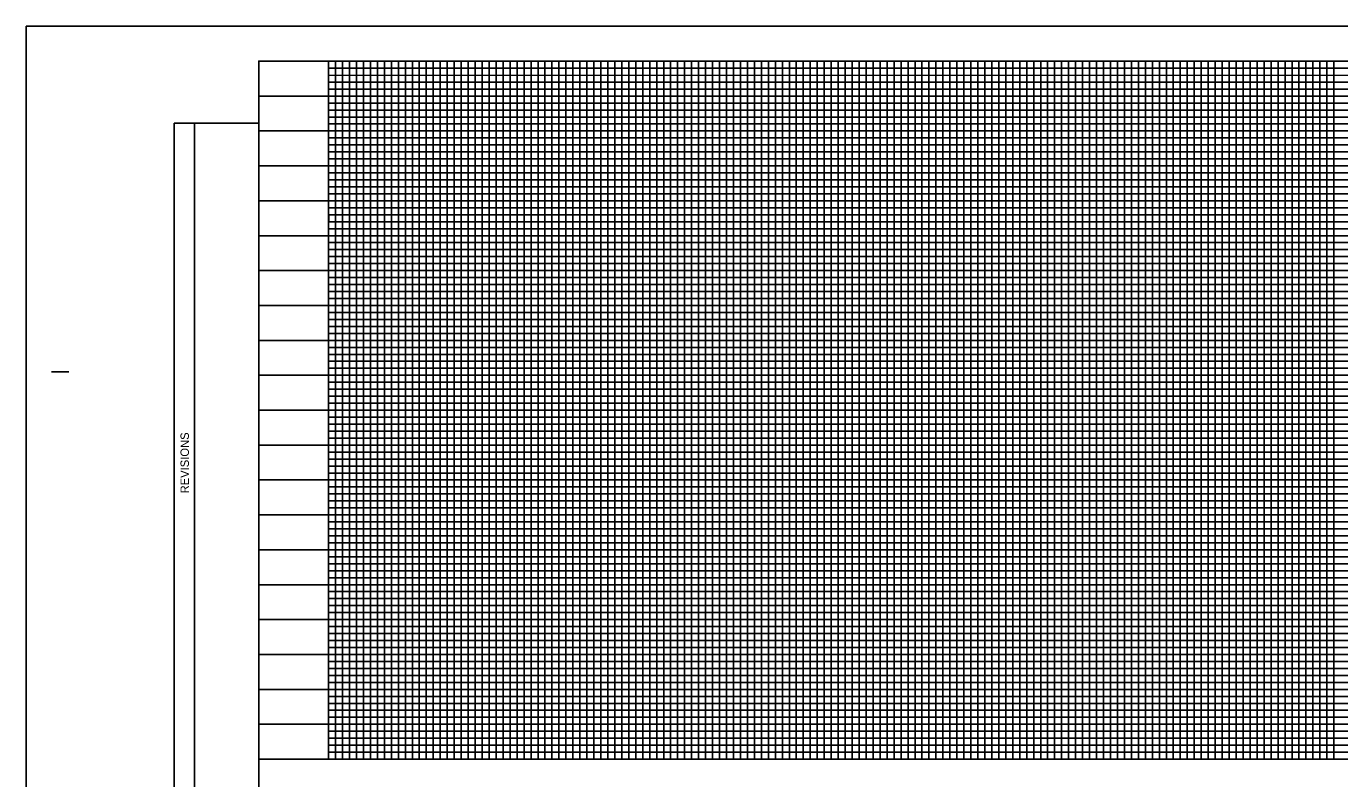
# Model space of a CAD drawing. Extents: x 2431000 to 2534000, y 645879 to 714000.
# Drawn here: x 2466807 to 2467748, y 669403 to 669942 of the extents above; entities that cross this region are included whole.
import ezdxf

# ---------------------------------------------------------------- set-up
doc = ezdxf.new("R2010")
doc.units = 0
for name, color, linetype in [('Sheet Block Revision CELL', 7, 'Continuous'), ('Sheet Clip Boundary CELL', 7, 'Continuous'), ('Sheet Plot Border Outside CELL', 7, 'Continuous'), ('Sheet Profile CELL', 7, 'Continuous'), ('Sheet Profile Grid Major CELL', 7, 'Continuous'), ('Sheet Profile Grid Middle CELL', 7, 'Continuous'), ('Sheet Profile Grid Minor CELL', 7, 'Continuous')]:
    doc.layers.add(name, color=color, linetype=linetype)

msp = doc.modelspace()

# ---------------------------------------------------------------- linework, layer by layer
at = {"layer": 'Sheet Block Revision CELL'}
for p, q in [((2466913.23, 669382.06), (2466913.23, 669872.71)), ((2466973.77, 669872.71), (2466913.23, 669872.71)), ((2466927.77, 669382.06), (2466927.77, 669872.72))]:
    msp.add_line(p, q, dxfattribs=at)
at = {"layer": 'Sheet Clip Boundary CELL'}
msp.add_lwpolyline([(2468456.5, 669779.51), (2468292.45, 669779.51), (2468292.45, 669917.06), (2467023.75, 669917.06), (2467023.75, 669417.06), (2468423.75, 669417.06), (2468423.75, 669779.51)], dxfattribs=at)
at = {"layer": 'Sheet Plot Border Outside CELL'}
msp.add_lwpolyline([(2466807.25, 668842.06), (2468490.75, 668842.06), (2468490.75, 669942.06), (2466807.25, 669942.06)], close=True, dxfattribs=at)
at = {"layer": 'Sheet Profile CELL'}
for p, q in [((2466825.25, 669694.56), (2466837.75, 669694.56)), ((2466973.75, 669417.06), (2468473.75, 669417.06)), ((2466973.75, 669417.06), (2468473.75, 669417.06))]:
    msp.add_line(p, q, dxfattribs=at)
msp.add_lwpolyline([(2468473.75, 669917.06), (2466973.75, 669917.06), (2466973.75, 668867.06), (2468473.75, 668867.06)], close=True, dxfattribs=at)
at = {"layer": 'Sheet Profile Grid Major CELL'}
msp.add_line((2466973.75, 669892.06), (2468173.75, 669892.06), dxfattribs=at)
for points in [[(2467023.75, 669917.06), (2467023.75, 669417.06), (2467073.75, 669417.06), (2467073.75, 669917.06), (2467123.75, 669917.06), (2467123.75, 669417.06), (2467173.75, 669417.06), (2467173.75, 669917.06), (2467223.75, 669917.06), (2467223.75, 669417.06), (2467273.75, 669417.06), (2467273.75, 669917.06), (2467323.75, 669917.06), (2467323.75, 669417.06), (2467373.75, 669417.06), (2467373.75, 669917.06), (2467423.75, 669917.06), (2467423.75, 669417.06), (2467473.75, 669417.06), (2467473.75, 669917.06), (2467523.75, 669917.06), (2467523.75, 669417.06), (2467573.75, 669417.06), (2467573.75, 669917.06), (2467623.75, 669917.06), (2467623.75, 669417.06), (2467673.75, 669417.06), (2467673.75, 669917.06), (2467723.75, 669917.06), (2467723.75, 669417.06), (2467773.75, 669417.06)], [(2466973.75, 669867.06), (2468173.75, 669867.06)], [(2468173.75, 669817.06), (2466973.75, 669817.06), (2466973.75, 669767.06), (2468473.75, 669767.06)], [(2468473.75, 669717.06), (2466973.75, 669717.06), (2466973.75, 669667.06), (2468473.75, 669667.06)], [(2468473.75, 669617.06), (2466973.75, 669617.06), (2466973.75, 669567.06), (2468473.75, 669567.06)], [(2468473.75, 669517.06), (2466973.75, 669517.06), (2466973.75, 669517.06), (2466973.75, 669467.06), (2468473.75, 669467.06)]]:
    msp.add_lwpolyline(points, dxfattribs=at)
at = {"layer": 'Sheet Profile Grid Middle CELL'}
for points in [[(2467048.75, 669917.06), (2467048.75, 669417.06), (2467098.75, 669417.06), (2467098.75, 669917.06), (2467148.75, 669917.06), (2467148.75, 669417.06), (2467198.75, 669417.06), (2467198.75, 669917.06), (2467248.75, 669917.06), (2467248.75, 669417.06), (2467298.75, 669417.06), (2467298.75, 669917.06), (2467348.75, 669917.06), (2467348.75, 669417.06), (2467398.75, 669417.06), (2467398.75, 669917.06), (2467448.75, 669917.06), (2467448.75, 669417.06), (2467498.75, 669417.06), (2467498.75, 669917.06), (2467548.75, 669917.06), (2467548.75, 669417.06), (2467598.75, 669417.06), (2467598.75, 669417.06), (2467598.75, 669917.06), (2467648.75, 669917.06), (2467648.75, 669417.06), (2467698.75, 669417.06), (2467698.75, 669917.06), (2467748.75, 669917.06)], [(2468173.75, 669842.06), (2466973.75, 669842.06), (2466973.75, 669792.06), (2468173.75, 669792.06)], [(2468473.75, 669742.06), (2466973.75, 669742.06), (2466973.75, 669692.06), (2468298.75, 669692.06)], [(2468473.75, 669642.06), (2466973.75, 669642.06), (2466973.75, 669592.06), (2468473.75, 669592.06)], [(2468473.75, 669542.06), (2466973.75, 669542.06), (2466973.75, 669492.06), (2468473.75, 669492.06)], [(2468473.75, 669442.06), (2466973.75, 669442.06)]]:
    msp.add_lwpolyline(points, dxfattribs=at)
at = {"layer": 'Sheet Profile Grid Minor CELL'}
for p, q in [((2467023.75, 669912.06), (2468173.75, 669912.06)), ((2467023.75, 669907.06), (2467023.75, 669907.06)), ((2468173.75, 669907.03), (2467023.75, 669906.71)), ((2467023.75, 669902.06), (2468173.75, 669902.06)), ((2468173.75, 669782.06), (2467023.75, 669782.06)), ((2468423.75, 669777.06), (2467023.75, 669777.06)), ((2468423.75, 669772.06), (2467023.75, 669772.06)), ((2467023.75, 669762.06), (2468423.75, 669762.06)), ((2468423.75, 669757.06), (2467023.75, 669757.06)), ((2467023.75, 669752.06), (2468423.75, 669752.06)), ((2468423.75, 669732.06), (2467023.75, 669732.06)), ((2467023.75, 669727.06), (2468423.75, 669727.06)), ((2468423.75, 669707.06), (2467023.75, 669707.06)), ((2467023.75, 669702.06), (2468423.75, 669702.06)), ((2468423.75, 669682.06), (2467023.75, 669682.06)), ((2467023.75, 669677.06), (2468423.75, 669677.06)), ((2468423.75, 669672.06), (2467023.75, 669672.06)), ((2467023.75, 669662.06), (2468423.75, 669662.06)), ((2468423.75, 669657.06), (2467023.75, 669657.06)), ((2467023.75, 669652.06), (2468423.75, 669652.06)), ((2468423.75, 669647.06), (2467023.75, 669647.06)), ((2467023.75, 669637.06), (2468423.75, 669637.06)), ((2468423.75, 669632.06), (2467023.75, 669632.06)), ((2467023.75, 669627.06), (2468423.75, 669627.06)), ((2468423.75, 669622.06), (2467023.75, 669622.06)), ((2467023.75, 669612.06), (2468423.75, 669612.06)), ((2468423.75, 669607.06), (2467023.75, 669607.06)), ((2467023.75, 669602.06), (2468423.75, 669602.06)), ((2468423.75, 669597.06), (2467023.75, 669597.06)), ((2467023.75, 669587.06), (2468423.75, 669587.06)), ((2468423.75, 669582.06), (2467023.75, 669582.06)), ((2467023.75, 669577.06), (2468423.75, 669577.06)), ((2468423.75, 669572.06), (2467023.75, 669572.06)), ((2467023.75, 669562.06), (2468423.75, 669562.06)), ((2468423.75, 669557.06), (2467023.75, 669557.06)), ((2467023.75, 669552.06), (2468423.75, 669552.06)), ((2468423.75, 669547.06), (2467023.75, 669547.06)), ((2467023.75, 669537.06), (2468423.75, 669537.06)), ((2468423.75, 669532.06), (2467023.75, 669532.06)), ((2468423.75, 669527.06), (2467023.75, 669527.06)), ((2468423.75, 669522.06), (2467023.75, 669522.06)), ((2467023.75, 669512.06), (2468423.75, 669512.06)), ((2468423.75, 669507.06), (2467023.75, 669507.06)), ((2467023.75, 669502.06), (2468423.75, 669502.06)), ((2468423.75, 669497.06), (2467023.75, 669497.06)), ((2467023.75, 669487.06), (2468423.75, 669487.06)), ((2468423.75, 669482.06), (2467023.75, 669482.06)), ((2467023.75, 669477.06), (2468423.75, 669477.06)), ((2468423.75, 669472.06), (2467023.75, 669472.06)), ((2467023.75, 669462.06), (2468423.75, 669462.06)), ((2468423.75, 669457.06), (2467023.75, 669457.06)), ((2467023.75, 669452.06), (2468423.75, 669452.06)), ((2468423.75, 669447.06), (2467023.75, 669447.06)), ((2467023.75, 669437.06), (2468423.75, 669437.06)), ((2468423.75, 669432.06), (2467023.75, 669432.06)), ((2467023.75, 669427.06), (2468423.75, 669427.06))]:
    msp.add_line(p, q, dxfattribs=at)
for points in [[(2466973.75, 669417.06), (2468168.75, 669417.06), (2468168.75, 669917.06)], [(2467028.75, 669917.06), (2467028.75, 669417.06), (2467033.75, 669417.06), (2467033.75, 669917.06), (2467038.75, 669917.06), (2467038.75, 669417.06), (2467043.75, 669417.06), (2467043.75, 669917.06), (2467053.75, 669917.06), (2467053.75, 669417.06), (2467058.75, 669417.06), (2467058.75, 669917.06), (2467063.75, 669917.06), (2467063.75, 669417.06), (2467068.75, 669417.06), (2467078.75, 669417.06), (2467083.75, 669417.06), (2467083.75, 669917.06), (2467088.75, 669917.06), (2467088.75, 669417.06), (2467093.75, 669417.06), (2467093.75, 669917.06), (2467103.75, 669917.06), (2467103.75, 669417.06), (2467108.75, 669417.06), (2467108.75, 669917.06), (2467113.75, 669917.06), (2467113.75, 669417.06), (2467118.75, 669417.06), (2467118.75, 669917.06), (2467128.75, 669917.06), (2467128.75, 669417.06), (2467133.75, 669417.06), (2467133.75, 669917.06), (2467138.75, 669917.06), (2467138.75, 669417.06), (2467143.75, 669417.06), (2467143.75, 669917.06), (2467153.75, 669917.06), (2467153.75, 669417.06), (2467158.75, 669417.06), (2467158.75, 669917.06), (2467163.75, 669917.06), (2467163.75, 669417.06), (2467168.75, 669417.06), (2467168.75, 669917.06), (2467178.75, 669917.06), (2467178.75, 669417.06), (2467183.75, 669417.06), (2467183.75, 669917.06), (2467188.75, 669917.06), (2467188.75, 669417.06), (2467193.75, 669417.06), (2467193.75, 669917.06), (2467203.75, 669917.06), (2467203.75, 669417.06), (2467208.75, 669417.06), (2467208.75, 669917.06), (2467213.75, 669917.06), (2467213.75, 669417.06), (2467218.75, 669417.06), (2467218.75, 669917.06), (2467228.75, 669917.06), (2467228.75, 669417.06), (2467233.75, 669417.06), (2467233.75, 669917.06), (2467238.75, 669917.06), (2467238.75, 669417.06)], [(2467068.75, 669417.06), (2467068.75, 669917.06), (2467078.75, 669917.06), (2467078.75, 669417.06)], [(2467238.75, 669417.06), (2467243.75, 669417.06), (2467243.75, 669917.06), (2467253.75, 669917.06), (2467253.75, 669417.06), (2467258.75, 669417.06), (2467258.75, 669917.06), (2467263.75, 669917.06), (2467263.75, 669417.06), (2467268.75, 669417.06), (2467268.75, 669917.06), (2467278.75, 669917.06), (2467278.75, 669417.06), (2467283.75, 669417.06), (2467283.75, 669917.06), (2467288.75, 669917.06), (2467288.75, 669417.06), (2467293.75, 669417.06), (2467293.75, 669917.06), (2467303.75, 669917.06), (2467303.75, 669417.06), (2467308.75, 669417.06), (2467308.75, 669917.06), (2467313.75, 669917.06), (2467313.75, 669417.06), (2467318.75, 669417.06), (2467318.75, 669917.06), (2467328.75, 669917.06), (2467328.75, 669417.06), (2467333.75, 669417.06), (2467333.75, 669917.06), (2467338.75, 669917.06), (2467338.75, 669417.06), (2467343.75, 669417.06), (2467343.75, 669917.06), (2467353.75, 669917.06), (2467353.75, 669417.06), (2467358.75, 669417.06), (2467358.75, 669917.06), (2467363.75, 669917.06), (2467363.75, 669417.06), (2467368.75, 669417.06), (2467368.75, 669917.06), (2467378.75, 669917.06), (2467378.75, 669417.06), (2467383.75, 669417.06), (2467383.75, 669917.06), (2467388.75, 669917.06), (2467388.75, 669417.06), (2467393.75, 669417.06), (2467393.75, 669917.06), (2467403.75, 669917.06), (2467403.75, 669417.06), (2467408.75, 669417.06), (2467408.75, 669917.06), (2467413.75, 669917.06), (2467413.75, 669417.06), (2467418.75, 669417.06), (2467418.75, 669917.06), (2467428.75, 669917.06), (2467428.75, 669417.06), (2467433.75, 669417.06), (2467433.75, 669917.06), (2467438.75, 669917.06), (2467438.75, 669417.06), (2467443.75, 669417.06), (2467443.75, 669917.06), (2467453.75, 669917.06), (2467453.75, 669417.06), (2467458.75, 669417.06), (2467458.75, 669917.06), (2467463.75, 669917.06), (2467463.75, 669417.06), (2467468.75, 669417.06), (2467468.75, 669917.06), (2467478.75, 669917.06), (2467478.75, 669417.06), (2467483.75, 669417.06), (2467483.75, 669917.06), (2467488.75, 669917.06), (2467488.75, 669417.06), (2467493.75, 669417.06), (2467493.75, 669917.06), (2467503.75, 669917.06), (2467503.75, 669417.06), (2467508.75, 669417.06), (2467508.75, 669917.06), (2467513.75, 669917.06), (2467513.75, 669417.06), (2467518.75, 669417.06), (2467518.75, 669917.06), (2467528.75, 669917.06), (2467528.75, 669417.06), (2467533.75, 669417.06), (2467533.75, 669917.06), (2467538.75, 669917.06), (2467538.75, 669417.06), (2467543.75, 669417.06), (2467543.75, 669917.06), (2467553.75, 669917.06)], [(2467553.75, 669917.06), (2467553.75, 669417.06), (2467558.75, 669417.06), (2467558.75, 669917.06), (2467563.75, 669917.06), (2467563.75, 669417.06), (2467568.75, 669417.06), (2467568.75, 669917.06), (2467578.75, 669917.06), (2467578.75, 669417.06), (2467583.75, 669417.06), (2467583.75, 669917.06), (2467588.75, 669917.06), (2467588.75, 669417.06), (2467593.75, 669417.06), (2467593.75, 669917.06), (2467603.75, 669917.06), (2467603.75, 669417.06), (2467608.75, 669417.06), (2467608.75, 669917.06), (2467613.75, 669917.06), (2467613.75, 669417.06), (2467618.75, 669417.06), (2467618.75, 669917.06), (2467628.75, 669917.06), (2467628.75, 669417.06), (2467633.75, 669417.06), (2467633.75, 669917.06), (2467638.75, 669917.06), (2467638.75, 669417.06), (2467643.75, 669417.06), (2467643.75, 669917.06), (2467653.75, 669917.06), (2467653.75, 669417.06), (2467658.75, 669417.06), (2467658.75, 669917.06), (2467663.75, 669917.06), (2467663.75, 669417.06), (2467668.75, 669417.06), (2467668.75, 669917.06), (2467678.75, 669917.06), (2467678.75, 669417.06), (2467678.75, 669417.06), (2467683.75, 669417.06), (2467683.75, 669917.06), (2467688.75, 669917.06), (2467688.75, 669417.06), (2467693.75, 669417.06), (2467693.75, 669917.06), (2467703.75, 669917.06), (2467703.75, 669417.06), (2467708.75, 669417.06), (2467708.75, 669917.06), (2467713.75, 669917.06), (2467713.75, 669417.06), (2467718.75, 669417.06), (2467718.75, 669917.06), (2467728.75, 669917.06), (2467728.75, 669417.06), (2467733.75, 669417.06), (2467733.75, 669917.06), (2467738.75, 669917.06), (2467738.75, 669417.06), (2467743.75, 669417.06), (2467743.75, 669917.06), (2467753.75, 669917.06)], [(2468173.75, 669897.06), (2467023.75, 669897.06), (2467023.75, 669887.06), (2468173.75, 669887.06)], [(2468173.75, 669882.06), (2467023.75, 669882.06), (2467023.75, 669877.06), (2468173.75, 669877.06)], [(2468173.75, 669872.06), (2467023.75, 669872.06), (2467023.75, 669862.06), (2468173.75, 669862.06)], [(2468173.75, 669857.06), (2467023.75, 669857.06), (2467023.75, 669852.06), (2468173.75, 669852.06)], [(2468173.75, 669847.06), (2467023.75, 669847.06), (2467023.75, 669837.06), (2468173.75, 669837.06)], [(2468173.75, 669832.06), (2467023.75, 669832.06), (2467023.75, 669827.06), (2468173.75, 669827.06)], [(2468173.75, 669822.06), (2467023.75, 669822.06), (2467023.75, 669812.06), (2468173.75, 669812.06)], [(2468173.75, 669806.96), (2467023.85, 669806.96), (2467023.85, 669802.06), (2468173.75, 669802.06)], [(2468173.75, 669797.06), (2467023.75, 669797.06), (2467023.75, 669787.06), (2468173.75, 669787.06)], [(2468423.75, 669747.06), (2467023.75, 669747.06), (2467023.75, 669737.06), (2468423.75, 669737.06)], [(2468423.75, 669722.06), (2467023.75, 669722.06), (2467023.75, 669712.06), (2468423.75, 669712.06)], [(2468423.75, 669697.06), (2467023.75, 669697.06), (2467023.75, 669687.06), (2468423.75, 669687.06)], [(2468423.75, 669422.06), (2467023.75, 669422.06)]]:
    msp.add_lwpolyline(points, dxfattribs=at)

# ---------------------------------------------------------------- texts
at = {"layer": 'Sheet Block Revision CELL'}
msp.add_text('REVISIONS', height=6, rotation=90, dxfattribs=at).set_placement((2466923.73, 669607.45))

doc.saveas('drawing.dxf')
